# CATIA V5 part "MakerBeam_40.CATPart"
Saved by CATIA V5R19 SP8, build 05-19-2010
Part number: Profilé Makebeam 40
Definition: Profilé Makebeam 40
Nomenclature: MakerBeam_100056
Bounding box of the stored display mesh (mm): x 0 to 40, y -5 to 5, z -5 to 5
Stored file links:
  D:\Documents\1_Travail\1 - ac-limoges.fr\ac-limoges.fr\Emmanuel Maynard - STI2D_Turgot\1 - IT-I2D\Activités_IT_Première\IT_3_Abris_bus\Maquettes numériques\Abribus_eleve\MakerBeam_40.CATPart
  C:\Program Files\Dassault Systemes\B19\win_b64\reffiles\standard\MetricThickPitch.txt
  D:\Documents\1_Travail\2- 2I2D\6 -  Ressources ITEC\Ressources Techniques\0-Maquettes numériques_Composants\Catalogue_Makeblock\Catalog_Makeblock\12_MakerBeam\TableMakerbeam.xls
  D:\Documents\1_Travail\2- 2I2D\6 -  Ressources ITEC\Ressources Techniques\0-Maquettes numériques_Composants\Catalogue_Makeblock\Catalog_Makeblock\12_MakerBeam\TableMakerbeam.txt
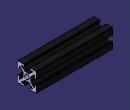
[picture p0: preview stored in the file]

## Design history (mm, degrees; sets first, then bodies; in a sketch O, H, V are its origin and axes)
Parameters
  Longueur = 40 mm
  `Désignation` = "Profilé Makebeam 40"
  `Référence` = "MakerBeam_100056"
AxisSystem1: origin (0, 0, 0), X (1, 0, 0), Y (0, 1, 0), Z (0, 0, 1)
Body1 (main body)
  Sketch1 on YZ plane of AxisSystem1, origin (0, 0, 0), H (0, 1, 0), V (0, 0, 1)
    line L1 (-5, 5) -> (-1.5, 5)
    point P1 (5, 5)
    point P2 (-5, 5)
    arc A1 centre (0, 0) radius 1.2 from (0, 1.2) to (-0.8485, 0.8485) ccw
    line L2 (-0.8485, 0.8485) -> (-5, 5)
    line L3 (0, 1.2) -> (0, 2)
    reference intersected line E1 through (0, 0) direction (-1, 0) from XY plane of AxisSystem1
    reference intersected line E2 through (0, 0) direction (0, 1) from ZX plane of AxisSystem1
    line L4 (-1.5, 5) -> (-1.5, 4)
    line L5 (-1.5, 4) -> (-3.2929, 4)
    line L6 (-3.2929, 4) -> (-1, 2)
    line L7 (-1, 2) -> (0, 2)
    reference projected line E3 through (0, 0) direction (0, 1) from edge [ZX plane of AxisSystem1 | YZ plane of AxisSystem1]
    radius A1 = 1.2
    distance L1 E1 = 5
    distance P2 E3 = 5
    distance L4 P2 = 3.5
    length L7 = 1
    distance L5 L1 = 1
    distance L7 L1 = 3
    angle L6 L3 = 48.903
    horizontal: L1 H, L5 H, L7 H
    vertical: L3 V, L4 V
    coincidence: L3 E2, L2 O
  Pad1: profile Sketch1, direction (1, 0, 0), length 40 {= Longueur}
  Fillet1: radius 0.2, on edge [face of Pad1 from Sketch1.L5 | face of Pad1 from Sketch1.L6]; edge [face of Pad1 from Sketch1.L6 | face of Pad1 from Sketch1.L7]; edge [face of Pad1 from Sketch1.L1 | face of Pad1 from Sketch1.L4]; edge [face of Pad1 from Sketch1.L4 | face of Pad1 from Sketch1.L5]
  Mirror1: of the body so far, about face of Pad1 from Sketch1.L2
  Fillet2: radius 0.2, on edge [face of Mirror1 | face of Pad1 from Sketch1.L1]
  Mirror2: of the body so far, about face of Mirror1
  Mirror3: of the body so far, about face of Pad1 from Sketch1.L3
  Sketch2 on face of Pad1, origin (40, 0.9666, 1.0824), H (0, 1, 0), V (0, 0, 1)
    point P1 (-0.9666, -1.0824)
    projected point E1 (-0.9666, -1.0824) from axis of face of Mirror3
    coincidence: E1 P1
  Hole1: placed by Sketch2, at (40, 0, 0) direction (-1, 0, 0), diameter 2.459, depth 10, threaded "M3", thread diameter 3, thread depth 8, pitch 0.5
  Sketch3 on face of Pad1, origin (0, -1.3866, 1.2369), H (0, 1, 0), V (0, 0, -1)
    point P1 (1.3866, 1.2369)
    reference projected point E1 (1.3866, 1.2369) from axis of face of Pad1
    coincidence: P1 E1
  Hole2: placed by Sketch3, at (0, 0, 0) direction (1, 0, 0), diameter 2.459, depth 10, threaded "M3", thread diameter 3, thread depth 8, pitch 0.5
Current feature: Mirror3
